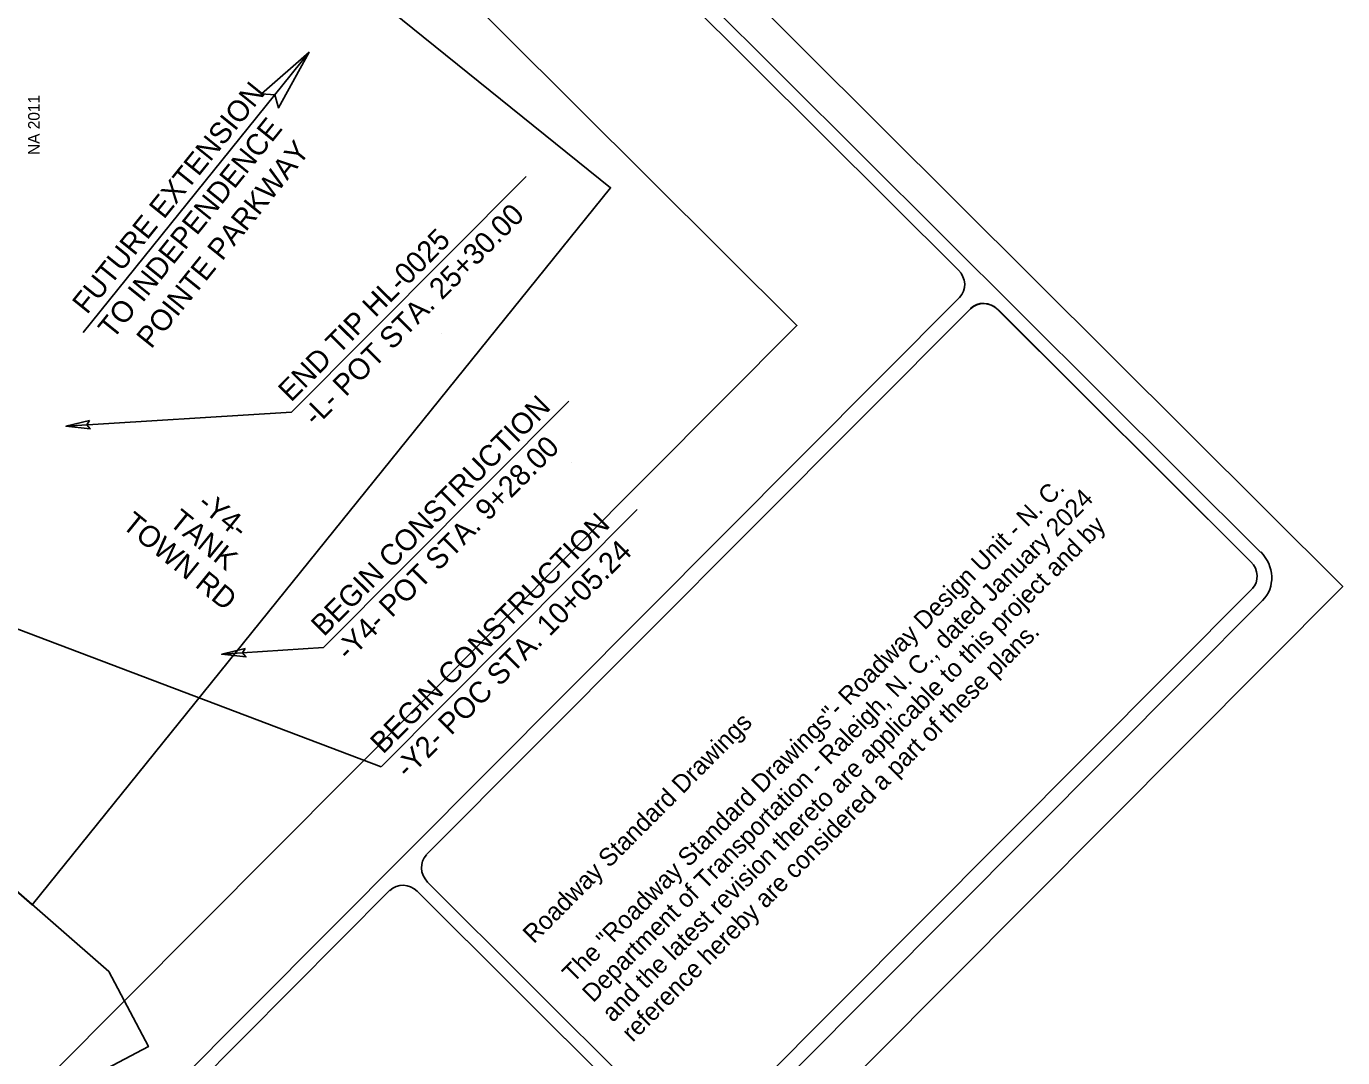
# Model space of a CAD drawing. Extents: x 1484932 to 1495672, y 495497 to 506262.
# Drawn here: x 1488841 to 1490835, y 498363 to 499926 of the extents above; entities that cross this region are included whole.
import ezdxf

# ---------------------------------------------------------------- set-up
doc = ezdxf.new("R2010")
doc.units = 0
for name, color, linetype in [('Old_Level_18', 7, 'Continuous'), ('Prop Dimension', 7, 'Continuous'), ('Prop DSN Text', 7, 'Continuous'), ('Prop DSN White Annotation Label', 7, 'Continuous'), ('Prop Horizontal Alignment Station Label', 7, 'Continuous'), ('Prop Terminator CELL', 7, 'Continuous'), ('Scratch_Level_4', 7, 'Continuous'), ('Sheet North Arrow CELL', 7, 'Continuous'), ('Sheet Plot Border Outside CELL', 7, 'Continuous')]:
    doc.layers.add(name, color=color, linetype=linetype)

msp = doc.modelspace()

# ---------------------------------------------------------------- linework, layer by layer
at = {"layer": 'Old_Level_18'}
for p, q in [((1488543.4, 501258.8), (1490253, 499556.3)), ((1490710.4, 499129.2), (1488558.1, 501272.7)), ((1487209.6, 496457.5), (1490254.5, 499515.1)), ((1489447, 498670.8), (1490271.3, 499498.4)), ((1490312.1, 499496.6), (1490695.8, 499114.5)), ((1490313.4, 499496.1), (1490695.8, 499114.5)), ((1490697.4, 499073.3), (1489873.5, 498246)), ((1489448.3, 498629.2), (1489831.9, 498247.1)), ((1488703, 497925.4), (1489391.5, 498616.8)), ((1489817.2, 498232.4), (1489432.7, 498615.3)), ((1489433.6, 498614.5), (1489817.2, 498232.4))]:
    msp.add_line(p, q, dxfattribs=at)
msp.add_lwpolyline([(1487537.4, 495866.7), (1490713.3, 499055.9)], dxfattribs=at)
for centre, major_axis, ratio, start_param, end_param in [((1490233.1, 499536.5), (21.4, -21.3), 0.927398, 0, 1.570796), ((1490292.7, 499476), (-21.9, 21.8), 0.927399, 4.712389, 6.283185), ((1490292.7, 499476), (-21.9, 21.8), 0.927399, 4.712389, 6.283185), ((1490292.6, 499476.9), (-21.4, 21.3), 0.927398, 4.712389, 6.283185), ((1490675.4, 499094), (-38.2, 38), 0.927398, 3.141593, 4.712389), ((1490676.2, 499094.8), (21.4, -21.3), 0.927398, 0, 1.570796), ((1489468.3, 498649.2), (-21.4, 21.3), 0.927398, 0, 1.570796), ((1489412.9, 498595.4), (-21.4, 21.3), 0.927398, 4.712389, 6.283185)]:
    msp.add_ellipse(centre, major_axis=major_axis, ratio=ratio, start_param=start_param, end_param=end_param, dxfattribs=at)
at = {"layer": 'Prop Dimension'}
for p, q in [((1489598, 499698.5), (1489242.3, 499341.4)), ((1489242.3, 499341.4), (1488900.6, 499320)), ((1489662.4, 499358), (1489290.8, 498984.9)), ((1489765.9, 499193.6), (1489377.9, 498804)), ((1489377.9, 498804), (1488775.9, 499031.9)), ((1489290.8, 498984.9), (1489136.5, 498974.4))]:
    msp.add_line(p, q, dxfattribs=at)
at = {"layer": 'Prop DSN Text'}
msp.add_line((1488926.4, 499461.8), (1489269, 499886.6), dxfattribs=at)
at = {"layer": 'Prop DSN White Annotation Label'}
for points in [[(1488865.6, 500011), (1488730.5, 500119.9), (1488058.3, 499286.4), (1488849.5, 498594.9), (1489725.7, 499681.3), (1489043.4, 500231.5)], [(1487208.7, 498608.1), (1488222.1, 499143.2), (1488965.4, 498493.7), (1489025.4, 498380), (1487698.9, 497679.6)]]:
    msp.add_lwpolyline(points, close=True, dxfattribs=at)
at = {"layer": 'Prop Terminator CELL'}
for points in [[(1489197, 499823.3), (1489269, 499886.6), (1489222.5, 499802.1), (1489217, 499822)], [(1488936.2, 499328.4), (1488900.6, 499320), (1488937.2, 499315.8), (1488932.2, 499321.9)], [(1489172, 498983), (1489136.5, 498974.4), (1489173.1, 498970.5), (1489168, 498976.5)]]:
    msp.add_lwpolyline(points, close=True, dxfattribs=at)
at = {"layer": 'Scratch_Level_4'}
for p, q in [((1489469.3, 499460.5), (1489469.3, 499460.5)), ((1489666.1, 499264.6), (1489666.1, 499264.6))]:
    msp.add_line(p, q, dxfattribs=at)
msp.add_lwpolyline([(1486969.7, 498427.7), (1489005, 500471.4), (1490008.1, 499472.4), (1487972.8, 497428.7)], close=True, dxfattribs=at)
at = {"layer": 'Sheet Plot Border Outside CELL'}
msp.add_lwpolyline([(1488496.6, 501405.6), (1484931.7, 497825.9), (1487270, 495497.3), (1490834.9, 499077)], close=True, dxfattribs=at)

# ---------------------------------------------------------------- texts
at = {"layer": 'Old_Level_18'}
for s, p in [('The "Roadway Standard Drawings"- Roadway Design Unit - N. C.', (1489669.2, 498475.3)), ('Department of Transportation - Raleigh, N. C., dated January 2024', (1489699.2, 498445.5)), ('and the latest revision thereto are applicable to this project and by', (1489729.1, 498415.7)), ('reference hereby are considered a part of these plans.', (1489759.1, 498385.8)), ('Roadway Standard Drawings', (1489609.3, 498535))]:
    msp.add_text(s, height=27.224, rotation=45.1186, dxfattribs=at).set_placement(p)
at = {"layer": 'Prop DSN Text'}
for s, rotation, p in [('FUTURE EXTENSION', 51.1158, (1488932.5, 499488.1)), ('TO INDEPENDENCE', 51.1158, (1488971.8, 499450.4)), ('POINTE PARKWAY', 51.1158, (1489029.7, 499435.9)), ('-L- POT STA. 25+30.00', 45.1191, (1489279, 499318.1)), ('END TIP HL-0025', 45.1191, (1489241.6, 499355.3)), ('BEGIN CONSTRUCTION', 45.1191, (1489291.4, 499000.1)), ('-Y4- POT STA. 9+28.00', 45.1191, (1489328.8, 498962.9)), ('BEGIN CONSTRUCTION', 45.1191, (1489381.1, 498822)), ('-Y2- POC STA. 10+05.24', 45.1191, (1489418.5, 498784.7))]:
    msp.add_text(s, height=32, rotation=rotation, dxfattribs=at).set_placement(p)
at = {"layer": 'Prop Horizontal Alignment Station Label'}
for s, p in [('-Y4-', (1489097.8, 499198.8)), ('TOWN RD', (1488983.8, 499167.6)), ('TANK', (1489055.2, 499171.6))]:
    msp.add_text(s, height=32, rotation=320.9673, dxfattribs=at).set_placement(p)
at = {"layer": 'Sheet North Arrow CELL'}
msp.add_text('NA 2011', height=17.5, rotation=89.9561, dxfattribs=at).set_placement((1488860.7, 499730.8))

doc.saveas('drawing.dxf')
